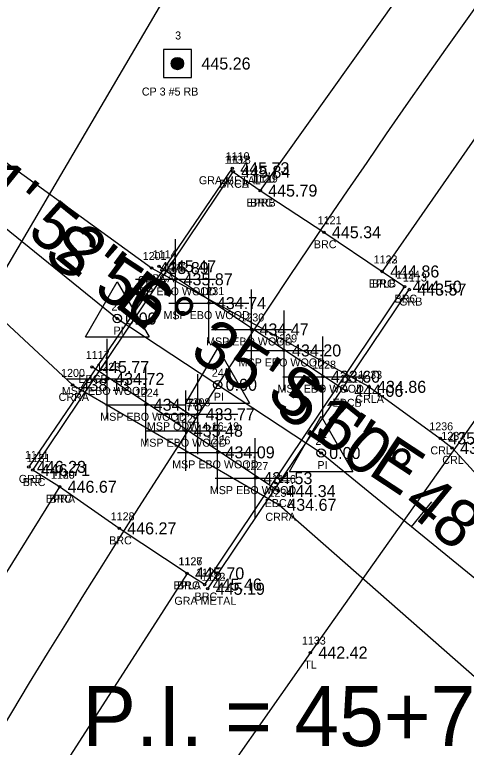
# Model space of a CAD drawing. Extents: x 1762456 to 1764480, y 822234 to 826541.
# Drawn here: x 1763452.5 to 1763508.9, y 824767.8 to 824859.3 of the extents above; entities that cross this region are included whole.
import ezdxf

# ---------------------------------------------------------------- set-up
doc = ezdxf.new("R2010")
doc.units = 0
for name, color, linetype in [('RD_EX_Bridge', 7, 'Continuous'), ('RD_EX_Bridge_txCode', 7, 'Continuous'), ('RD_EX_GuardRail', 7, 'Continuous'), ('RD_EX_GuardRail_txCode', 7, 'Continuous'), ('RD_EX_H2O', 7, 'Continuous'), ('RD_EX_H2O_txCode', 7, 'Continuous'), ('RD_EX_Road', 7, 'Continuous'), ('RD_EX_Road_txCode', 7, 'Continuous'), ('RD_EX_TX_Bridge_ELEV', 7, 'Continuous'), ('RD_EX_TX_GuardRail_ELEV', 7, 'Continuous'), ('RD_EX_TX_H2O_ELEV', 7, 'Continuous'), ('RD_EX_TX_Road_ELEV', 7, 'Continuous'), ('RD_EX_TX_VEG_ELEV', 7, 'Continuous'), ('RD_EX_VEG', 7, 'Continuous'), ('RD_EX_VEG_txCode', 7, 'Continuous'), ('RD_HC_Cl', 7, 'Continuous'), ('RD_HC_Data', 7, 'Continuous'), ('RD_HC_Data_Tic', 7, 'Continuous'), ('RD_HC_Survey', 7, 'Continuous'), ('RD_HC_Survey_ELEV', 7, 'Continuous'), ('RD_HC_Survey_txCode', 7, 'Continuous'), ('RD_HC_txCode', 7, 'Continuous'), ('RD_SMD_Locator', 7, 'Continuous')]:
    doc.layers.add(name, color=color, linetype=linetype)

msp = doc.modelspace()

# ---------------------------------------------------------------- linework, layer by layer
at = {"layer": 'RD_EX_Bridge'}
for p, q in [((1763472.638, 824821.271), (1763472.638, 824831.271)), ((1763476.797, 824818.301), (1763476.797, 824828.301)), ((1763470.558, 824827.9), (1763493.938, 824812.355)), ((1763467.638, 824826.271), (1763477.638, 824826.271)), ((1763482.115, 824815.009), (1763482.115, 824825.009)), ((1763471.797, 824823.301), (1763481.797, 824823.301)), ((1763486.178, 824812.393), (1763486.178, 824822.393)), ((1763477.115, 824820.009), (1763487.115, 824820.009)), ((1763491.036, 824809.115), (1763491.036, 824819.115)), ((1763464.098, 824808.84), (1763464.098, 824818.84)), ((1763481.178, 824817.393), (1763491.178, 824817.393)), ((1763485.48, 824799.838), (1763462.21, 824815.339)), ((1763468.907, 824805.611), (1763468.907, 824815.611)), ((1763459.098, 824813.84), (1763469.098, 824813.84)), ((1763486.036, 824814.115), (1763496.036, 824814.115)), ((1763473.911, 824802.371), (1763473.911, 824812.371)), ((1763463.907, 824810.611), (1763473.907, 824810.611)), ((1763477.877, 824799.668), (1763477.877, 824809.668)), ((1763468.911, 824807.371), (1763478.911, 824807.371)), ((1763482.587, 824796.451), (1763482.587, 824806.451)), ((1763472.877, 824804.668), (1763482.877, 824804.668)), ((1763477.587, 824801.451), (1763487.587, 824801.451))]:
    msp.add_line(p, q, dxfattribs=at)
msp.add_lwpolyline([(1763479.827, 824839.695), (1763483.203, 824837.348), (1763491.159, 824832.146), (1763498.427, 824827.249), (1763501.224, 824825.355), (1763476.268, 824788.166), (1763474.076, 824789.564), (1763465.603, 824795.179), (1763458.16, 824800.377), (1763454.813, 824802.459), (1763479.827, 824839.695)], dxfattribs=at)
for centre in [(1763472.638, 824826.271), (1763476.797, 824823.301), (1763482.115, 824820.009), (1763486.178, 824817.393), (1763464.098, 824813.84), (1763491.036, 824814.115), (1763468.907, 824810.611), (1763473.911, 824807.371), (1763477.877, 824804.668), (1763482.587, 824801.451)]:
    msp.add_circle(centre, 0.15, dxfattribs=at)
at = {"layer": 'RD_EX_GuardRail'}
for p, q in [((1763479.717, 824840.137), (1763454.318, 824802.853)), ((1763476.654, 824787.637), (1763501.813, 824824.996))]:
    msp.add_line(p, q, dxfattribs=at)
at = {"layer": 'RD_EX_H2O'}
for p, q in [((1763496.792, 824812.847), (1763469.636, 824827.682)), ((1763475.397, 824804.422), (1763475.397, 824814.422)), ((1763459.772, 824813.085), (1763485.591, 824798.12)), ((1763470.397, 824809.422), (1763480.397, 824809.422))]:
    msp.add_line(p, q, dxfattribs=at)
for points in [[(1763469.636, 824827.682), (1763444.913, 824845.549), (1763435.48, 824853.424), (1763401.744, 824907.762), (1763323.186, 824974.273), (1763226.748, 825015.177), (1763219.023, 825018.483), (1763206.388, 825014.434), (1763109.021, 824967.635), (1763091.899, 824957.317), (1763081.742, 824947.35), (1763046.143, 824865.154)], [(1763459.772, 824813.085), (1763437.298, 824833.984), (1763421.73, 824846.888), (1763391.202, 824896.666), (1763313.159, 824962.885), (1763227.897, 824997.524), (1763208.457, 824998.223), (1763114.183, 824952.916), (1763092.864, 824935.952), (1763064.348, 824852.134)], [(1763496.792, 824812.847), (1763505.685, 824806.416), (1763507.164, 824805.227), (1763521.579, 824789.488), (1763543.544, 824765.508), (1763572.145, 824752.095), (1763662.415, 824704.478), (1763697.558, 824670.472), (1763707.927, 824630.757), (1763723.525, 824595.874), (1763766.818, 824582.67), (1763818.294, 824585.487), (1763920.084, 824604.11)], [(1763485.591, 824798.12), (1763510.281, 824776.411), (1763530.733, 824746.573), (1763546.507, 824728.759), (1763647.946, 824677.163), (1763661.458, 824680.215), (1763679.149, 824659.291), (1763688.377, 824626.339), (1763689.04, 824599.45), (1763710.73, 824574.271), (1763740.297, 824562.002), (1763762.69, 824555.256), (1763820.302, 824563.648), (1763926.687, 824582.302)]]:
    msp.add_lwpolyline(points, dxfattribs=at)
msp.add_circle((1763475.397, 824809.422), 0.15, dxfattribs=at)
at = {"layer": 'RD_EX_Road'}
for points in [[(1763951.028, 825365.438), (1763882.121, 825291.587), (1763813.301, 825217.444), (1763784.22, 825184.639), (1763754.382, 825152.478), (1763744.668, 825142.842), (1763675.267, 825070.174), (1763607.457, 824995.533), (1763574.265, 824958.093), (1763542.372, 824919.201), (1763512.113, 824877.957), (1763483.203, 824837.348)], [(1763963.891, 825353.592), (1763895.682, 825279.081), (1763827.34, 825205.219), (1763758.38, 825131.335), (1763689.427, 825057.327), (1763653.535, 825018.753), (1763637.74, 825000.803), (1763620.709, 824983.807), (1763588.782, 824946.603), (1763557.13, 824907.379), (1763526.523, 824867.674), (1763498.427, 824827.249)], [(1763458.16, 824800.377), (1763430.998, 824756.746), (1763406.015, 824711.899), (1763384.237, 824666.742), (1763362.807, 824620.839), (1763342.792, 824574.998), (1763324.892, 824528.785), (1763288.297, 824435.223), (1763252.087, 824341.052), (1763216.313, 824245.876), (1763180.374, 824152.327)], [(1763474.076, 824789.564), (1763447.078, 824747.547), (1763422.649, 824703.331), (1763399.597, 824659.261), (1763379.309, 824614.364), (1763364.489, 824579.397), (1763364.489, 824579.397), (1763359.36, 824568.521), (1763347.678, 824537.953), (1763341.79, 824522.257), (1763305.937, 824428.62), (1763270.168, 824334.759), (1763235.029, 824239.84), (1763198.429, 824144.729)]]:
    msp.add_lwpolyline(points, dxfattribs=at)
at = {"layer": 'RD_EX_VEG'}
for points in [[(1763566.804, 824996.313), (1763552.477, 824977.489), (1763517.791, 824940.661), (1763441.019, 824809.917), (1763409.908, 824765.774), (1763387.308, 824719.585), (1763364.334, 824675.154), (1763345.198, 824627.763), (1763325.757, 824580.46), (1763306.335, 824535.898), (1763266.935, 824443.239), (1763235.968, 824345.204), (1763198.019, 824250.85), (1763166.498, 824157.968)], [(1763654.174, 824981.39), (1763637.841, 824967.614), (1763603.039, 824934.549), (1763572.899, 824896.618), (1763543.523, 824856.037), (1763489.474, 824779.675), (1763459.285, 824736.58), (1763444.879, 824693.265), (1763423.623, 824647.114), (1763401.17, 824604.963), (1763396.878, 824581.151)]]:
    msp.add_lwpolyline(points, dxfattribs=at)
at = {"layer": 'RD_HC_Cl'}
for p, q in [((1763429.743, 824850.185), (1763465.361, 824821.375)), ((1763465.361, 824821.375), (1763490.817, 824804.588)), ((1763490.817, 824804.588), (1763517.555, 824782.789))]:
    msp.add_line(p, q, dxfattribs=at)
msp.add_arc((1764677.021, 824029.626), 1432.392, 137.053176, 159.117629, dxfattribs=at)
at = {"layer": 'RD_HC_Data'}
for p, q in [((1763461.39, 824819.082), (1763465.362, 824825.962)), ((1763465.362, 824825.962), (1763469.331, 824819.082)), ((1763461.39, 824819.082), (1763469.331, 824819.082)), ((1763473.926, 824810.816), (1763477.898, 824817.695)), ((1763477.898, 824817.695), (1763481.866, 824810.816)), ((1763473.926, 824810.816), (1763481.866, 824810.816)), ((1763486.846, 824802.295), (1763490.818, 824809.175)), ((1763490.818, 824809.175), (1763494.787, 824802.295)), ((1763486.846, 824802.295), (1763494.787, 824802.295))]:
    msp.add_line(p, q, dxfattribs=at)
for centre in [(1763465.361, 824821.375), (1763477.896, 824813.108), (1763490.817, 824804.588)]:
    msp.add_circle(centre, 0.529, dxfattribs=at)
at = {"layer": 'RD_HC_Data_Tic'}
for p, q in [((1763475.166, 824808.914), (1763471.809, 824811.09)), ((1763502.104, 824795.386), (1763504.632, 824798.486))]:
    msp.add_line(p, q, dxfattribs=at)
at = {"layer": 'RD_HC_Survey'}
for p, q in [((1763472.266, 824852.729), (1763472.266, 824853.693)), ((1763472.29, 824852.699), (1763472.29, 824853.722)), ((1763472.315, 824852.673), (1763472.315, 824853.748)), ((1763472.34, 824852.649), (1763472.34, 824853.773)), ((1763472.365, 824852.627), (1763472.365, 824853.795)), ((1763472.389, 824852.606), (1763472.389, 824853.815)), ((1763472.414, 824852.588), (1763472.414, 824853.834)), ((1763472.439, 824852.57), (1763472.439, 824853.851)), ((1763472.464, 824852.554), (1763472.464, 824853.867)), ((1763472.488, 824852.54), (1763472.488, 824853.881)), ((1763472.513, 824852.527), (1763472.513, 824853.895)), ((1763472.538, 824852.514), (1763472.538, 824853.907)), ((1763472.563, 824852.503), (1763472.563, 824853.918)), ((1763472.587, 824852.493), (1763472.587, 824853.928)), ((1763472.612, 824852.484), (1763472.612, 824853.937)), ((1763472.637, 824852.476), (1763472.637, 824853.945)), ((1763472.662, 824852.469), (1763472.662, 824853.953)), ((1763472.686, 824852.462), (1763472.686, 824853.959)), ((1763472.711, 824852.457), (1763472.711, 824853.965)), ((1763472.736, 824852.452), (1763472.736, 824853.969)), ((1763472.761, 824852.448), (1763472.761, 824853.973)), ((1763472.785, 824852.445), (1763472.785, 824853.976)), ((1763472.81, 824852.443), (1763472.81, 824853.978)), ((1763472.835, 824852.442), (1763472.835, 824853.98)), ((1763472.86, 824852.441), (1763472.86, 824853.98)), ((1763472.884, 824852.441), (1763472.884, 824853.98)), ((1763472.909, 824852.442), (1763472.909, 824853.979)), ((1763472.934, 824852.444), (1763472.934, 824853.977)), ((1763472.959, 824852.447), (1763472.959, 824853.975)), ((1763472.983, 824852.45), (1763472.983, 824853.971)), ((1763473.008, 824852.455), (1763473.008, 824853.967)), ((1763473.033, 824852.46), (1763473.033, 824853.962)), ((1763473.058, 824852.466), (1763473.058, 824853.956)), ((1763473.082, 824852.472), (1763473.082, 824853.949)), ((1763473.107, 824852.48), (1763473.107, 824853.941)), ((1763473.132, 824852.489), (1763473.132, 824853.933)), ((1763473.157, 824852.498), (1763473.157, 824853.923)), ((1763473.181, 824852.509), (1763473.181, 824853.912)), ((1763473.206, 824852.521), (1763473.206, 824853.901)), ((1763473.231, 824852.533), (1763473.231, 824853.888)), ((1763473.256, 824852.547), (1763473.256, 824853.874)), ((1763473.28, 824852.563), (1763473.28, 824853.859)), ((1763473.305, 824852.579), (1763473.305, 824853.842)), ((1763473.33, 824852.597), (1763473.33, 824853.824)), ((1763473.355, 824852.617), (1763473.355, 824853.805)), ((1763473.379, 824852.638), (1763473.379, 824853.783)), ((1763473.404, 824852.661), (1763473.404, 824853.76)), ((1763473.429, 824852.687), (1763473.429, 824853.735)), ((1763473.454, 824852.714), (1763473.454, 824853.707)), ((1763472.117, 824853.032), (1763472.117, 824853.39)), ((1763472.142, 824852.949), (1763472.142, 824853.472)), ((1763472.167, 824852.889), (1763472.167, 824853.533)), ((1763472.191, 824852.84), (1763472.191, 824853.582)), ((1763472.216, 824852.798), (1763472.216, 824853.624)), ((1763472.241, 824852.761), (1763472.241, 824853.66)), ((1763473.478, 824852.745), (1763473.478, 824853.676)), ((1763473.503, 824852.78), (1763473.503, 824853.642)), ((1763473.528, 824852.819), (1763473.528, 824853.602)), ((1763473.553, 824852.864), (1763473.553, 824853.557)), ((1763473.577, 824852.918), (1763473.577, 824853.503)), ((1763473.602, 824852.988), (1763473.602, 824853.433)), ((1763473.627, 824853.099), (1763473.627, 824853.322))]:
    msp.add_line(p, q, dxfattribs=at)
msp.add_lwpolyline([(1763474.616, 824854.961), (1763471.116, 824854.961), (1763471.116, 824851.461), (1763474.616, 824851.461)], close=True, dxfattribs=at)
msp.add_circle((1763472.866, 824853.211), 0.769, dxfattribs=at)
at = {"layer": 'RD_SMD_Locator'}
for centre in [(1763472.866, 824853.211), (1763479.717, 824840.137), (1763479.827, 824839.695), (1763479.827, 824839.695), (1763483.203, 824837.348), (1763483.203, 824837.348), (1763491.159, 824832.146), (1763469.636, 824827.682), (1763470.558, 824827.9), (1763498.427, 824827.249), (1763498.427, 824827.249), (1763501.224, 824825.355), (1763501.813, 824824.996), (1763465.361, 824821.375), (1763462.21, 824815.339), (1763459.772, 824813.085), (1763477.896, 824813.108), (1763496.792, 824812.847), (1763493.938, 824812.355), (1763505.685, 824806.416), (1763507.164, 824805.227), (1763490.817, 824804.588), (1763454.318, 824802.853), (1763454.813, 824802.459), (1763458.16, 824800.377), (1763458.16, 824800.377), (1763485.48, 824799.838), (1763485.591, 824798.12), (1763465.603, 824795.179), (1763474.076, 824789.564), (1763474.076, 824789.564), (1763476.268, 824788.166), (1763476.654, 824787.637), (1763489.474, 824779.675)]:
    msp.add_circle(centre, 0.15, dxfattribs=at)

# ---------------------------------------------------------------- texts
at = {"layer": 'RD_EX_Bridge_txCode'}
for s, p in [('1132', (1763478.764, 824840.695)), ('1118', (1763479.047, 824840.695)), ('1119', (1763482.424, 824838.348)), ('BRCA', (1763478.087, 824837.695)), ('BRCB', (1763478.102, 824837.695)), ('BRC', (1763481.951, 824835.348)), ('1121', (1763490.38, 824833.146)), ('BRC', (1763489.907, 824830.146)), ('1114', (1763469.778, 824828.9)), ('1122', (1763497.364, 824828.249)), ('1232', (1763471.291, 824827.271)), ('1124', (1763500.161, 824826.355)), ('EBCA', (1763468.841, 824825.9)), ('BRC', (1763497.175, 824825.249)), ('MSP EBO WOOD', (1763466.968, 824824.271)), ('1231', (1763475.734, 824824.301)), ('BRC', (1763499.972, 824823.355)), ('MSP EBO WOOD', (1763471.127, 824821.301)), ('1230', (1763480.729, 824821.009)), ('MSP EBO WOOD', (1763476.446, 824818.009)), ('1229', (1763484.832, 824818.393)), ('1117', (1763461.43, 824816.339)), ('MSP EBO WOOD', (1763480.509, 824815.393)), ('1223', (1763462.752, 824814.84)), ('1228', (1763489.689, 824815.115)), ('EBCB', (1763460.509, 824813.339)), ('1115', (1763493.158, 824813.355)), ('MSP EBO WOOD', (1763458.429, 824811.84)), ('1224', (1763467.561, 824811.611)), ('MSP EBO WOOD', (1763485.366, 824812.115)), ('EBCB', (1763492.237, 824810.355)), ('MSP EBO WOOD', (1763463.238, 824808.611)), ('1225', (1763472.565, 824808.371)), ('MSP EBO WOOD', (1763468.242, 824805.371)), ('1226', (1763476.507, 824805.668)), ('1131', (1763454.034, 824803.459)), ('MSP EBO WOOD', (1763472.208, 824802.668)), ('1227', (1763481.241, 824802.451)), ('1129', (1763457.097, 824801.377)), ('1116', (1763484.676, 824800.838)), ('BRC', (1763453.561, 824800.459)), ('MSP EBO WOOD', (1763476.918, 824799.451)), ('BRC', (1763456.908, 824798.377)), ('EBCA', (1763483.763, 824797.838)), ('1128', (1763464.54, 824796.179)), ('BRC', (1763464.351, 824793.179)), ('1126', (1763472.99, 824790.564)), ('1125', (1763475.205, 824789.166)), ('BRC', (1763472.824, 824787.564)), ('BRC', (1763475.016, 824786.166))]:
    msp.add_text(s, height=1, dxfattribs=at).set_placement(p)
at = {"layer": 'RD_EX_GuardRail_txCode'}
for s, p in [('1110', (1763478.898, 824841.137)), ('GRA METAL', (1763475.551, 824838.137)), ('1113', (1763501.033, 824825.996)), ('GRB', (1763500.561, 824822.996)), ('1111', (1763453.821, 824803.853)), ('GRB', (1763453.066, 824800.853)), ('1112', (1763475.875, 824788.637)), ('GRA METAL', (1763472.489, 824785.637))]:
    msp.add_text(s, height=1, dxfattribs=at).set_placement(p)
at = {"layer": 'RD_EX_H2O_txCode'}
for s, p in [('1201', (1763468.533, 824828.682)), ('CRLA', (1763467.919, 824825.682)), ('1200', (1763458.347, 824814.085)), ('1233', (1763495.446, 824813.847)), ('CRRA', (1763458.032, 824811.085)), ('CRLA', (1763495.076, 824810.847)), ('1208', (1763474.011, 824810.422)), ('MSP ODW 4-16-19', (1763469.058, 824807.422)), ('1236', (1763504.315, 824807.416)), ('1237', (1763505.817, 824806.227)), ('CRL', (1763504.457, 824804.416)), ('CRL', (1763505.935, 824803.227)), ('1234', (1763484.245, 824799.12)), ('CRRA', (1763483.851, 824796.12))]:
    msp.add_text(s, height=1, dxfattribs=at).set_placement(p)
at = {"layer": 'RD_EX_Road_txCode'}
for s, p in [('1120', (1763482.101, 824838.348)), ('EPRB', (1763481.502, 824835.348)), ('1123', (1763497.364, 824828.249)), ('EPLB', (1763496.75, 824825.249)), ('1130', (1763457.058, 824801.377)), ('EPRA', (1763456.444, 824798.377)), ('1127', (1763473.013, 824790.564)), ('EPLA', (1763472.383, 824787.564))]:
    msp.add_text(s, height=1, dxfattribs=at).set_placement(p)
at = {"layer": 'RD_EX_TX_Bridge_ELEV'}
for s, p in [('445.84', (1763480.827, 824838.945)), ('445.84', (1763480.827, 824838.945)), ('445.79', (1763484.203, 824836.598)), ('445.34', (1763492.159, 824831.396)), ('445.47', (1763471.558, 824827.15)), ('444.86', (1763499.427, 824826.499)), ('435.87', (1763473.638, 824825.521)), ('444.50', (1763502.224, 824824.605)), ('434.74', (1763477.797, 824822.551)), ('434.47', (1763483.115, 824819.259)), ('434.20', (1763487.178, 824816.643)), ('445.77', (1763463.21, 824814.589)), ('434.72', (1763465.098, 824813.09)), ('433.60', (1763492.036, 824813.365)), ('444.06', (1763494.938, 824811.605)), ('434.78', (1763469.907, 824809.861)), ('435.48', (1763474.911, 824806.621)), ('434.09', (1763478.877, 824803.918)), ('446.71', (1763455.813, 824801.709)), ('434.53', (1763483.587, 824800.701)), ('446.67', (1763459.16, 824799.627)), ('444.34', (1763486.48, 824799.088)), ('446.27', (1763466.603, 824794.429)), ('445.70', (1763475.076, 824788.814)), ('445.46', (1763477.268, 824787.416))]:
    msp.add_text(s, height=1.5, dxfattribs=at).set_placement(p)
at = {"layer": 'RD_EX_TX_GuardRail_ELEV'}
for s, p in [('445.73', (1763480.717, 824839.387)), ('443.57', (1763502.813, 824824.246)), ('446.23', (1763455.318, 824802.103)), ('445.19', (1763477.654, 824786.887))]:
    msp.add_text(s, height=1.5, dxfattribs=at).set_placement(p)
at = {"layer": 'RD_EX_TX_H2O_ELEV'}
for s, p in [('435.89', (1763470.636, 824826.932)), ('438.13', (1763460.772, 824812.335)), ('434.86', (1763497.792, 824812.097)), ('433.77', (1763476.397, 824808.672)), ('435.92', (1763506.685, 824805.666)), ('436.00', (1763508.164, 824804.477)), ('434.67', (1763486.591, 824797.37))]:
    msp.add_text(s, height=1.5, dxfattribs=at).set_placement(p)
at = {"layer": 'RD_EX_TX_Road_ELEV'}
for s, p in [('445.79', (1763484.203, 824836.598)), ('444.86', (1763499.427, 824826.499)), ('446.67', (1763459.16, 824799.627)), ('445.70', (1763475.076, 824788.814))]:
    msp.add_text(s, height=1.5, dxfattribs=at).set_placement(p)
at = {"layer": 'RD_EX_TX_VEG_ELEV'}
msp.add_text('442.42', height=1.5, dxfattribs=at).set_placement((1763490.474, 824778.925))
at = {"layer": 'RD_EX_VEG_txCode'}
for s, p in [('1133', (1763488.411, 824780.675)), ('TL', (1763488.703, 824777.675))]:
    msp.add_text(s, height=1, dxfattribs=at).set_placement(p)
at = {"layer": 'RD_HC_Data'}
for s, rotation, p in [('S 51%%d 01\' 52" E', 321.03112, (1763427, 824853.69)), ('S 56%%d 35\' 51" E', 326.5976, (1763455.896, 824828.814)), ('S 50%%d 48\' 38" E', 320.81043, (1763483.703, 824811.678))]:
    msp.add_text(s, height=6, rotation=rotation, dxfattribs=at).set_placement(p)
msp.add_text('P.I. = 45+77.34', height=7.5, dxfattribs=at).set_placement((1763461, 824768))
at = {"layer": 'RD_HC_Survey_ELEV'}
for s, p in [('445.26', (1763475.866, 824852.461)), ('0.00', (1763466.361, 824820.625)), ('0.00', (1763478.896, 824812.358)), ('0.00', (1763491.817, 824803.838))]:
    msp.add_text(s, height=1.5, dxfattribs=at).set_placement(p)
at = {"layer": 'RD_HC_Survey_txCode'}
for s, p in [('3', (1763472.582, 824856.211)), ('CP 3 #5 RB', (1763468.425, 824849.211))]:
    msp.add_text(s, height=1, dxfattribs=at).set_placement(p)
at = {"layer": 'RD_HC_txCode'}
for s, p in [('23', (1763464.628, 824822.375)), ('PI', (1763464.888, 824819.375)), ('24', (1763477.164, 824814.108)), ('PI', (1763477.424, 824811.108)), ('25', (1763490.085, 824805.588)), ('PI', (1763490.344, 824802.588))]:
    msp.add_text(s, height=1, dxfattribs=at).set_placement(p)

doc.saveas('drawing.dxf')
